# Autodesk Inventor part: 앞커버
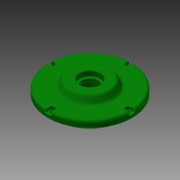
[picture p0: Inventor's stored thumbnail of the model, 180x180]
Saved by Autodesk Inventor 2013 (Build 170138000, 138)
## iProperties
Created: 2016-11
Part Number: 앞커버
Material: 알루미늄 6061
Document SubType Name: Modeling
Designer: mduedu
Density: 2.71 g/cm^3
Mass: 470.684 g
Surface Area: 413.208 cm^2
Volume: 173.684 cm^3
Author: mduedu
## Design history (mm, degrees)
sketch "스케치1"
  geometry: L1 (30, -16)-(30, -30); L2 (30, -30)-(20, -35.774); L3 (20, -35.774)-(20, -65); L4 (20, -65)-(10, -65); L5 (10, -65)-(10, -53); L6 (10, -53)-(0, -53); L7 (0, -53)-(0, -23.5); L8 (0, 0)-(30, 0); L9 (14, -23.5)-(14, -20.5); L10 (14, -20.5)-(17, -20.5); L11 (17, -20.5)-(17, -12.5); L12 (0, -23.5)-(14, -23.5); L13 (21.7, -16)-(30, -16); L14 (21.7, -16)-(21.7, -12.5); L15 (21.7, -12.5)-(17, -12.5)
  constraints: 30 end point, 8 parallel, 5 perpendicular, 2 horizontal, 2 vertical alignment
  dimensions: "d0" = 10 distance of L5.end L6.end; "d2" = 10 distance of L3.end L4.end; "d3" = 10 distance between parallel lines of L1 L3; "d4" = 120 deg angle of L3 L2; "d6" = 60 diameter of L1.end L8; "d7" = 41 diameter of L10 L8; "d8" = 47 diameter of L12 L8; "d9" = 32 diameter of L13 L8; "d10" = 106 diameter of L6 L8; "d11" = 130 diameter of L4 L8; "d64" = 14 distance between parallel lines of L9 L7; "d65" = 3 distance of L9.end L10.end; "d66" = 8.3 distance of L13.start L1.start; "d67" = 25 diameter of L15 L8
revolve "회전1" sketch "스케치1" stored, may be unused: angle "d12" = 90 deg
fillet "모깎기1" dims "d13" = 1
fillet "모깎기2" dims "d14" = 3
chamfer "모따기1" distance "d15" = 1; stored, may be unused: second distance "d16" = 2, angle "d17" = 45 deg
fillet "모깎기3" dims "d18" = 0.3
chamfer "모따기2" distance "d36" = 0.8; stored, may be unused: second distance "d37" = 2, angle "d38" = 30 deg
sketch "스케치3"
  geometry: C1 r 65 at (0, 0) reference; A1 r 59 centre (0, 0) between (0, 59) and (59, 0); 2 further points
  constraints: 4 point on circle, 2 horizontal alignment, 2 vertical alignment, 1 centre point, 1 coincident
  dimensions: "d33" = 118 diameter of A1
sketch "스케치4"
  geometry: 4 further points
  constraints: 4 other
hole "구멍2" sketch "스케치4" at (0, 59), (-59, 0), (59, 0), (0, -59) diameter "d39" = 4.5; stored, may be unused: countersink angle "d43" = 90 deg, drill point angle "d45" = 0 deg; dims "d40" = 6, "d41" = 8, "d42" = 5, "d44" = 8
sketch "스케치6"
  geometry: L1 (-4, 5.877)-(-4, 0); L2 (4, 5.877)-(4, 0); A1 r 4 centre (0, 0) between (-2.712, 2.941) and (2.712, 2.941) reference; A2 r 65 centre (0, -59) between (-4, 5.877) and (4, 5.877) reference; 1 further point
  constraints: 4 end point, 4 point on circle, 2 tangent, 2 vertical
extrude "돌출2" cut sketch "스케치6" stored distance "d51" = 10; taper "d52" = 0 deg
fillet "모깎기5" dims "d56" = 0.3
fillet "모깎기6" dims "d57" = 0.3
sketch "스케치5"
  geometry: C1 r 30 at (0, 0); C2 r 47.5 at (0, 0); 1 further point
  constraints: 2 centre point, 2 coincident
  dimensions: "d46" = 60 diameter of C1; "d47" = 95 diameter of C2
extrude "돌출1" cut sketch "스케치5" distance "d48" = 10; taper "d49" = 0 deg
fillet "모깎기4" dims "d50" = 3
node "솔리드1"
pattern_circular "원형 패턴1" dims angle "d54" = 360 deg
pattern_circular "원형 패턴2" dims angle "d59" = 360 deg
pattern_circular "원형 패턴3" dims angle "d62" = 360 deg
